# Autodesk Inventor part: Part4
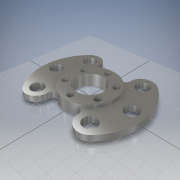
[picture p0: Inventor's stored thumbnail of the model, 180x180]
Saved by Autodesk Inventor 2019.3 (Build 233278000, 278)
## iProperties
Created: 2019-02
Part Number: Part4
Material: Nickel-Copper Alloy 400
Document SubType Name: Modeling
Designer: Synergysoft
Density: 8.83 g/cm^3
Appearance: Chrome - Polished
Author: Synergysoft
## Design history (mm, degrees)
sketch "Sketch1" dims "d1" = 70, "d8" = 140
  geometry: C1 r 25 at (0, 0); C2 r 5 at (0, -35); C3 r 5 at (30.311, -17.5); C4 r 5 at (30.311, 17.5); C5 r 5 at (0, 35); C6 r 5 at (-30.311, 17.5); C7 r 5 at (-30.311, -17.5); C8 r 11 at (70, 0); C9 r 11 at (49.497, 49.497); C10 r 11 at (0, 70); C11 r 11 at (-49.497, 49.497); C12 r 11 at (-70, 0); C13 r 11 at (-49.497, -49.497); C14 r 11 at (0, -70); C15 r 11 at (49.497, -49.497); A1 r 45 centre (0, 0) between (18.27, -41.124) and (-18.27, -41.124); A2 r 20 centre (49.497, -49.497) between (29.512, -48.739) and (63.64, -63.64); A3 r 8 centre (21.518, -48.435) between (29.512, -48.739) and (18.27, -41.124); A4 r 20 centre (49.497, 49.497) between (29.512, 48.739) and (63.64, 63.64); A5 r 20 centre (-49.497, 49.497) between (-29.512, 48.739) and (-63.64, 63.64); A6 r 20 centre (-49.497, -49.497) between (-29.512, -48.739) and (-63.64, -63.64); A7 r 8 centre (-21.518, -48.435) between (-18.27, -41.124) and (-29.512, -48.739); A8 r 8 centre (21.518, 48.435) between (18.27, 41.124) and (29.512, 48.739); A9 r 8 centre (-21.518, 48.435) between (-29.512, 48.739) and (-18.27, 41.124); A10 r 90 centre (0, 0) between (63.64, -63.64) and (63.64, 63.64); A11 r 90 centre (0, 0) between (-63.64, 63.64) and (-63.64, -63.64); 3 further points
  constraints: 26 centre point, 24 point on circle, 9 coincident, 8 tangent, 2 horizontal alignment, 2 vertical alignment, 34 other
  dimensions: "d0" = 50 diameter of C1; "d2" = 90 diameter of A1; "d3" = 10 diameter of C2; "d6" = 360 deg dimension on point (0, 0) C2.centre (derived); "d10" = 22 diameter of C8; "d13" = 360 deg dimension on point (0, 0) C8.centre (derived); "d15" = 20 radius of A2; "d16" = 8 radius of A3; "d17" = 20 radius of A4; "d18" = 20 radius of A5; "d19" = 20 radius of A6; "d20" = 8 radius of A7; "d21" = 8 radius of A8; "d22" = 8 radius of A9; "d23" = 90 radius of A10; "d24" = 90 radius of A11
extrude "Extrusion1" new body sketch "Sketch1" stored distance "d25" = 10; taper "d26" = 0 deg
extrude "Extrusion2" join sketch "Sketch1" stored distance "d27" = 20; taper "d28" = 0 deg
body "Solid1"
